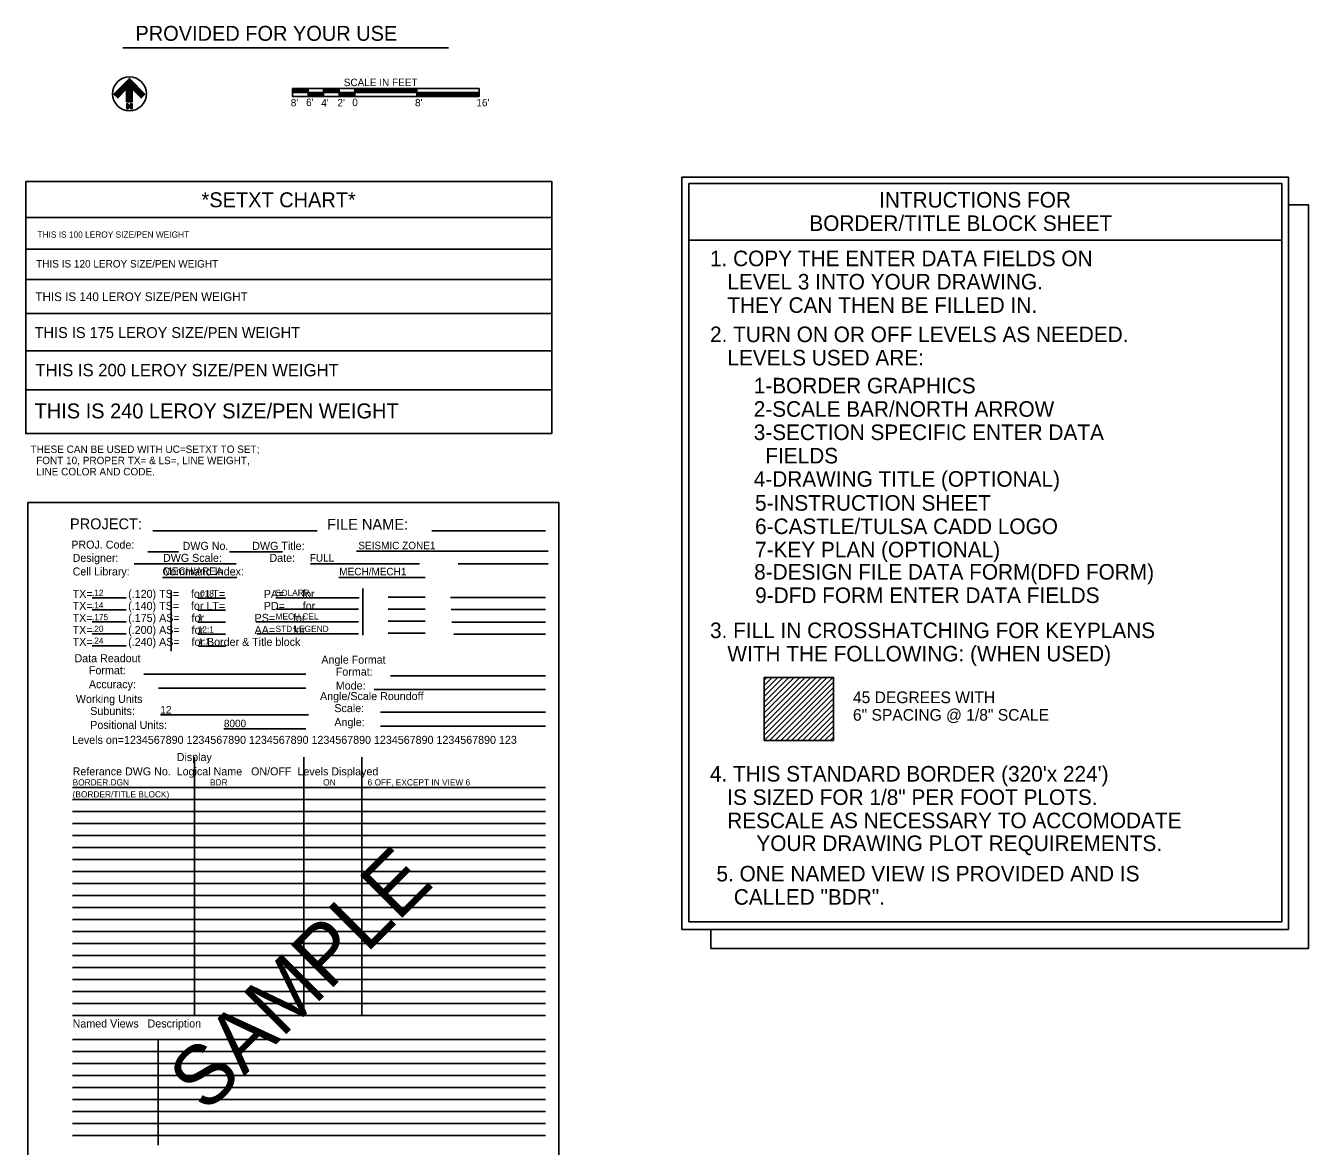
# Model space of a CAD drawing. Extents: x 10040.55 to 10045.84, y 10033.26 to 10035.76.
# Drawn here: x 10044.118 to 10045.836, y 10034.254 to 10035.755 of the extents above; entities that cross this region are included whole.
import ezdxf

# ---------------------------------------------------------------- set-up
doc = ezdxf.new("R2010")
doc.units = 0
for name, color, linetype in [('Level 1', 7, 'Continuous'), ('Level 2', 7, 'Continuous'), ('Level 5', 7, 'Continuous'), ('Level 8', 7, 'Continuous'), ('Level 9', 7, 'Continuous')]:
    doc.layers.add(name, color=color, linetype=linetype)

msp = doc.modelspace()

# ---------------------------------------------------------------- linework, layer by layer
at = {"layer": 'Level 2'}
for p, q in [((10044.2569, 10035.6528), (10044.2569, 10035.6841)), ((10044.4753, 10035.6705), (10044.7253, 10035.6705)), ((10044.4753, 10035.6705), (10044.4753, 10035.6601)), ((10044.4753, 10035.67), (10044.4961, 10035.67)), ((10044.4753, 10035.6691), (10044.4961, 10035.6691)), ((10044.4753, 10035.6683), (10044.4961, 10035.6683)), ((10044.4753, 10035.6674), (10044.4961, 10035.6674)), ((10044.4753, 10035.6665), (10044.4961, 10035.6665)), ((10044.4753, 10035.6657), (10044.4961, 10035.6657)), ((10044.4753, 10035.6653), (10044.7253, 10035.6653)), ((10044.4961, 10035.6705), (10044.4961, 10035.6601)), ((10044.4961, 10035.6649), (10044.5169, 10035.6649)), ((10044.4961, 10035.664), (10044.5169, 10035.664)), ((10044.5169, 10035.6705), (10044.5169, 10035.6601)), ((10044.5169, 10035.67), (10044.5377, 10035.67)), ((10044.5169, 10035.6691), (10044.5377, 10035.6691)), ((10044.5169, 10035.6682), (10044.5377, 10035.6682)), ((10044.5169, 10035.6674), (10044.5377, 10035.6674)), ((10044.5169, 10035.6665), (10044.5377, 10035.6665)), ((10044.5169, 10035.6656), (10044.5377, 10035.6656)), ((10044.5377, 10035.6648), (10044.5586, 10035.6648)), ((10044.5377, 10035.664), (10044.5586, 10035.664)), ((10044.5378, 10035.6705), (10044.5378, 10035.6601)), ((10044.5586, 10035.6705), (10044.5586, 10035.6601)), ((10044.5586, 10035.6699), (10044.6419, 10035.6699)), ((10044.5586, 10035.669), (10044.6419, 10035.669)), ((10044.5586, 10035.6681), (10044.6419, 10035.6681)), ((10044.5586, 10035.6673), (10044.6419, 10035.6673)), ((10044.5586, 10035.6664), (10044.6419, 10035.6664)), ((10044.6419, 10035.6705), (10044.6419, 10035.6601)), ((10044.6419, 10035.6645), (10044.7252, 10035.6645)), ((10044.7253, 10035.6705), (10044.7253, 10035.6601)), ((10044.254, 10035.6436), (10044.254, 10035.6501)), ((10044.2546, 10035.6436), (10044.2546, 10035.6501)), ((10044.2546, 10035.6498), (10044.2592, 10035.644)), ((10044.2592, 10035.6436), (10044.2592, 10035.6501)), ((10044.2598, 10035.6436), (10044.2598, 10035.6501)), ((10044.4753, 10035.6601), (10044.7253, 10035.6601)), ((10044.4961, 10035.6631), (10044.5169, 10035.6631)), ((10044.4961, 10035.6623), (10044.5169, 10035.6623)), ((10044.4961, 10035.6614), (10044.5169, 10035.6614)), ((10044.4961, 10035.6605), (10044.5169, 10035.6605)), ((10044.5377, 10035.6631), (10044.5586, 10035.6631)), ((10044.5377, 10035.6622), (10044.5586, 10035.6622)), ((10044.5377, 10035.6614), (10044.5586, 10035.6614)), ((10044.5377, 10035.6605), (10044.5586, 10035.6605)), ((10044.6419, 10035.6636), (10044.7252, 10035.6636)), ((10044.6419, 10035.6628), (10044.7252, 10035.6628)), ((10044.6419, 10035.6619), (10044.7252, 10035.6619)), ((10044.6419, 10035.661), (10044.7252, 10035.661))]:
    msp.add_line(p, q, dxfattribs=at)
for points in [[(10044.2606, 10035.6528), (10044.2606, 10035.67), (10044.2725, 10035.658), (10044.2777, 10035.6632), (10044.2569, 10035.6841), (10044.2361, 10035.6632), (10044.2413, 10035.658), (10044.2532, 10035.67), (10044.2532, 10035.6528)], [(10044.2534, 10035.6436), (10044.2534, 10035.6501), (10044.2548, 10035.6501), (10044.2586, 10035.6454), (10044.2586, 10035.6501), (10044.2604, 10035.6501), (10044.2604, 10035.6436), (10044.2589, 10035.6436), (10044.2552, 10035.6484), (10044.2552, 10035.6436)]]:
    msp.add_lwpolyline(points, close=True, dxfattribs=at)
for points in [[(10044.2367, 10035.6626), (10044.2569, 10035.6828), (10044.2771, 10035.6626)], [(10044.2374, 10035.6619), (10044.2569, 10035.6815), (10044.2764, 10035.6619)], [(10044.238, 10035.6613), (10044.2569, 10035.6802), (10044.2758, 10035.6613)], [(10044.2387, 10035.6606), (10044.2569, 10035.6789), (10044.2751, 10035.6606)], [(10044.256, 10035.6528), (10044.256, 10035.6767), (10044.2393, 10035.66)], [(10044.255, 10035.6528), (10044.255, 10035.6744), (10044.24, 10035.6593)], [(10044.2541, 10035.6528), (10044.2541, 10035.6722), (10044.2406, 10035.6587)], [(10044.2532, 10035.6528), (10044.2532, 10035.67), (10044.2413, 10035.658)], [(10044.2578, 10035.6528), (10044.2578, 10035.6767), (10044.2745, 10035.66)], [(10044.2587, 10035.6528), (10044.2587, 10035.6744), (10044.2738, 10035.6593)], [(10044.2597, 10035.6528), (10044.2597, 10035.6722), (10044.2732, 10035.6587)]]:
    msp.add_lwpolyline(points, dxfattribs=at)
msp.add_circle((10044.257, 10035.6635), 0.0227, dxfattribs=at)
at = {"layer": 'Level 5'}
for p, q in [((10044.2483, 10035.7253), (10044.6844, 10035.7253)), ((10044.118, 10035.4979), (10044.8225, 10035.4979)), ((10045.0062, 10035.4674), (10045.8002, 10035.4674)), ((10044.118, 10035.4554), (10044.8225, 10035.4554)), ((10044.118, 10035.4147), (10044.8225, 10035.4147)), ((10044.118, 10035.3693), (10044.8225, 10035.3693)), ((10044.118, 10035.3192), (10044.8225, 10035.3192)), ((10044.118, 10035.2672), (10044.8225, 10035.2672)), ((10045.1067, 10034.8342), (10045.1546, 10034.882)), ((10045.1067, 10034.8121), (10045.1766, 10034.8819)), ((10045.1068, 10034.8564), (10045.1325, 10034.8821)), ((10045.1068, 10034.8048), (10045.184, 10034.8819)), ((10045.1068, 10034.8637), (10045.1248, 10034.8817)), ((10045.1069, 10034.8418), (10045.1473, 10034.8821)), ((10045.1069, 10034.8786), (10045.1104, 10034.8821)), ((10045.1069, 10034.8491), (10045.1399, 10034.882)), ((10045.1069, 10034.8712), (10045.1177, 10034.882)), ((10045.1069, 10034.8196), (10045.169, 10034.8817)), ((10045.107, 10034.7976), (10045.1915, 10034.8821)), ((10045.107, 10034.8271), (10045.1619, 10034.882)), ((10045.1142, 10034.7974), (10045.1988, 10034.8821)), ((10045.1216, 10034.7974), (10045.1997, 10034.8756)), ((10045.1293, 10034.7978), (10045.1996, 10034.8681)), ((10045.1365, 10034.7977), (10045.1996, 10034.8608)), ((10045.1438, 10034.7976), (10045.1995, 10034.8533)), ((10045.1511, 10034.7976), (10045.1995, 10034.846)), ((10045.1584, 10034.7975), (10045.1995, 10034.8386)), ((10045.1658, 10034.7975), (10045.1998, 10034.8315)), ((10045.1731, 10034.7975), (10045.1996, 10034.824)), ((10045.1804, 10034.7973), (10045.1998, 10034.8167)), ((10045.188, 10034.7976), (10045.1997, 10034.8093)), ((10045.1953, 10034.7976), (10045.1998, 10034.802))]:
    msp.add_line(p, q, dxfattribs=at)
for points in [[(10044.118, 10035.5462), (10044.8225, 10035.5462), (10044.8225, 10035.2086), (10044.118, 10035.2086), (10044.118, 10035.5462)], [(10044.9969, 10035.552), (10045.8091, 10035.552), (10045.8091, 10034.5446), (10044.9969, 10034.5446), (10044.9969, 10035.552)], [(10045.0062, 10035.5436), (10045.8002, 10035.5436), (10045.8002, 10034.5547), (10045.0062, 10034.5547), (10045.0062, 10035.5436)], [(10045.8091, 10035.515), (10045.8358, 10035.515), (10045.8358, 10034.5191), (10045.0356, 10034.5191), (10045.0356, 10034.5446)]]:
    msp.add_lwpolyline(points, dxfattribs=at)
msp.add_lwpolyline([(10045.107, 10034.7976), (10045.107, 10034.8821), (10045.1998, 10034.8821), (10045.1998, 10034.7976)], close=True, dxfattribs=at)
at = {"layer": 'Level 8'}
for p, q in [((10044.1209, 10033.283), (10044.1209, 10035.1163)), ((10044.1209, 10035.1163), (10044.832, 10035.1163)), ((10044.832, 10035.1163), (10044.832, 10033.283)), ((10044.5083, 10035.0783), (10044.2883, 10035.0783)), ((10044.814, 10035.0783), (10044.6621, 10035.0783)), ((10044.3228, 10035.0504), (10044.2814, 10035.0504)), ((10044.4619, 10035.0504), (10044.3911, 10035.0504)), ((10044.8176, 10035.0511), (10044.5611, 10035.0511)), ((10044.2634, 10035.0342), (10044.3998, 10035.0342)), ((10044.4996, 10035.0342), (10044.6454, 10035.0342)), ((10044.6974, 10035.0342), (10044.8176, 10035.0342)), ((10044.3012, 10035.016), (10044.401, 10035.016)), ((10044.5374, 10035.016), (10044.6531, 10035.016)), ((10044.3127, 10034.9971), (10044.3127, 10034.9174)), ((10044.5696, 10034.9386), (10044.5696, 10035.0013)), ((10044.2524, 10034.9886), (10044.2071, 10034.9886)), ((10044.3855, 10034.9881), (10044.3485, 10034.9881)), ((10044.5644, 10034.9888), (10044.4531, 10034.9888)), ((10044.6532, 10034.9895), (10044.6033, 10034.9895)), ((10044.814, 10034.9889), (10044.6869, 10034.9889)), ((10044.2524, 10034.9725), (10044.2071, 10034.9725)), ((10044.3855, 10034.9721), (10044.3485, 10034.9721)), ((10044.5639, 10034.9733), (10044.4543, 10034.9733)), ((10044.6532, 10034.9734), (10044.6033, 10034.9734)), ((10044.814, 10034.9729), (10044.688, 10034.9729)), ((10044.2524, 10034.9564), (10044.2071, 10034.9564)), ((10044.3855, 10034.956), (10044.3485, 10034.956)), ((10044.5639, 10034.9567), (10044.4266, 10034.9567)), ((10044.6532, 10034.9573), (10044.6033, 10034.9573)), ((10044.814, 10034.9562), (10044.6885, 10034.9562)), ((10044.2524, 10034.9403), (10044.2071, 10034.9403)), ((10044.3855, 10034.9399), (10044.3485, 10034.9399)), ((10044.5639, 10034.9406), (10044.4277, 10034.9406)), ((10044.6532, 10034.9412), (10044.6033, 10034.9412)), ((10044.814, 10034.9402), (10044.6913, 10034.9402)), ((10044.2524, 10034.9243), (10044.2071, 10034.9243)), ((10044.3855, 10034.9238), (10044.3496, 10034.9238)), ((10044.493, 10034.8863), (10044.2763, 10034.8863)), ((10044.6066, 10034.8844), (10044.814, 10034.8844)), ((10044.493, 10034.8676), (10044.2958, 10034.8676)), ((10044.814, 10034.8658), (10044.5845, 10034.8658)), ((10044.4966, 10034.8318), (10044.2984, 10034.8318)), ((10044.814, 10034.8356), (10044.593, 10034.8356)), ((10044.493, 10034.8131), (10044.3836, 10034.8131)), ((10044.814, 10034.8169), (10044.593, 10034.8169)), ((10044.3441, 10034.7754), (10044.3441, 10034.4294)), ((10044.4904, 10034.7754), (10044.4904, 10034.4305)), ((10044.5681, 10034.7754), (10044.5681, 10034.4294)), ((10044.814, 10034.7348), (10044.1809, 10034.7348)), ((10044.814, 10034.7188), (10044.1809, 10034.7188)), ((10044.814, 10034.7027), (10044.1809, 10034.7027)), ((10044.814, 10034.6866), (10044.1809, 10034.6866)), ((10044.814, 10034.6705), (10044.1809, 10034.6705)), ((10044.814, 10034.6545), (10044.1809, 10034.6545)), ((10044.814, 10034.6384), (10044.1809, 10034.6384)), ((10044.814, 10034.6223), (10044.1809, 10034.6223)), ((10044.814, 10034.6062), (10044.1809, 10034.6062)), ((10044.814, 10034.5902), (10044.1809, 10034.5902)), ((10044.814, 10034.5741), (10044.1809, 10034.5741)), ((10044.814, 10034.558), (10044.1809, 10034.558)), ((10044.814, 10034.5419), (10044.1809, 10034.5419)), ((10044.814, 10034.5259), (10044.1809, 10034.5259)), ((10044.814, 10034.5098), (10044.1809, 10034.5098)), ((10044.814, 10034.4937), (10044.1809, 10034.4937)), ((10044.814, 10034.4776), (10044.1809, 10034.4776)), ((10044.814, 10034.4616), (10044.1809, 10034.4616)), ((10044.814, 10034.4455), (10044.1809, 10034.4455)), ((10044.814, 10034.4294), (10044.1809, 10034.4294)), ((10044.814, 10034.3973), (10044.1809, 10034.3973)), ((10044.2953, 10034.3973), (10044.2953, 10034.2558)), ((10044.814, 10034.3812), (10044.1809, 10034.3812)), ((10044.814, 10034.3651), (10044.1809, 10034.3651)), ((10044.814, 10034.349), (10044.1809, 10034.349)), ((10044.814, 10034.3329), (10044.1809, 10034.3329)), ((10044.814, 10034.3169), (10044.1809, 10034.3169)), ((10044.814, 10034.3008), (10044.1809, 10034.3008)), ((10044.814, 10034.2847), (10044.1809, 10034.2847)), ((10044.814, 10034.2686), (10044.1809, 10034.2686))]:
    msp.add_line(p, q, dxfattribs=at)

# ---------------------------------------------------------------- texts
at = {"layer": 'Level 1'}
msp.add_text('SAMPLE', height=0.08, rotation=45, dxfattribs=at).set_placement((10044.3598, 10034.2973))
at = {"layer": 'Level 2'}
for s, p in [('SCALE IN FEET', (10044.544, 10035.6738)), ("8'", (10044.473, 10035.6467)), ("6'", (10044.4935, 10035.647)), ("4'", (10044.5138, 10035.6464)), ("2'", (10044.5355, 10035.6467)), ('0', (10044.5554, 10035.647)), ("8'", (10044.6394, 10035.6467)), ("16'", (10044.7216, 10035.6467))]:
    msp.add_text(s, height=0.01, dxfattribs=at).set_placement(p)
at = {"layer": 'Level 5'}
for s, height, p in [('PROVIDED FOR YOUR USE', 0.02, (10044.265, 10035.7345)), ('*SETXT CHART*', 0.02, (10044.3535, 10035.5116)), ('INTRUCTIONS FOR', 0.020833, (10045.2609, 10035.5112)), ('BORDER/TITLE BLOCK SHEET', 0.020833, (10045.1675, 10035.4799)), ('THIS IS 100 LEROY SIZE/PEN WEIGHT', 0.008333, (10044.1338, 10035.4709)), ('THIS IS 120 LEROY SIZE/PEN WEIGHT', 0.01, (10044.1321, 10035.4309)), ('1. COPY THE ENTER DATA FIELDS ON', 0.020833, (10045.0344, 10035.4327)), ('   LEVEL 3 INTO YOUR DRAWING.', 0.020833, (10045.0344, 10035.4015)), ('THIS IS 140 LEROY SIZE/PEN WEIGHT', 0.011667, (10044.131, 10035.386)), ('   THEY CAN THEN BE FILLED IN.', 0.020833, (10045.0344, 10035.3702)), ('THIS IS 175 LEROY SIZE/PEN WEIGHT', 0.014583, (10044.13, 10035.3365)), ('2. TURN ON OR OFF LEVELS AS NEEDED.', 0.020833, (10045.0345, 10035.331)), ('   LEVELS USED ARE:', 0.020833, (10045.0345, 10035.2998)), ('THIS IS 200 LEROY SIZE/PEN WEIGHT', 0.016667, (10044.131, 10035.2852)), ('1-BORDER GRAPHICS', 0.020833, (10045.093, 10035.2624)), ('2-SCALE BAR/NORTH ARROW', 0.020833, (10045.093, 10035.2311)), ('THIS IS 240 LEROY SIZE/PEN WEIGHT', 0.02, (10044.13, 10035.2289)), ('3-SECTION SPECIFIC ENTER DATA', 0.020833, (10045.093, 10035.1999)), ('THESE CAN BE USED WITH UC=SETXT TO SET;', 0.01, (10044.1246, 10035.1826)), ('  FIELDS', 0.02083, (10045.093, 10035.1686)), ('  FONT 10, PROPER TX= & LS=, LINE WEIGHT,', 0.01, (10044.1246, 10035.1676)), ('  LINE COLOR AND CODE.', 0.01, (10044.1246, 10035.1526)), ('4-DRAWING TITLE (OPTIONAL)', 0.020833, (10045.093, 10035.1374)), ('5-INSTRUCTION SHEET', 0.020833, (10045.0948, 10035.1053)), ('6-CASTLE/TULSA CADD LOGO', 0.020833, (10045.0948, 10035.074)), ('7-KEY PLAN (OPTIONAL)', 0.020833, (10045.0948, 10035.0428)), ('8-DESIGN FILE DATA FORM(DFD FORM)', 0.020833, (10045.0936, 10035.013)), ('9-DFD FORM ENTER DATA FIELDS', 0.020833, (10045.0949, 10034.9817)), ('3. FILL IN CROSSHATCHING FOR KEYPLANS', 0.020833, (10045.0345, 10034.9347)), ('   WITH THE FOLLOWING: (WHEN USED)', 0.020833, (10045.0345, 10034.9035)), ('45 DEGREES WITH', 0.015625, (10045.2259, 10034.8476)), ('6" SPACING @ 1/8" SCALE', 0.015625, (10045.2259, 10034.8241)), ("4. THIS STANDARD BORDER (320'x 224')", 0.020833, (10045.0343, 10034.7426)), ('   IS SIZED FOR 1/8" PER FOOT PLOTS.', 0.020833, (10045.0343, 10034.7113)), ('   RESCALE AS NECESSARY TO ACCOMODATE', 0.020833, (10045.0343, 10034.6801)), ('YOUR DRAWING PLOT REQUIREMENTS.', 0.020833, (10045.0966, 10034.6496)), ('5. ONE NAMED VIEW IS PROVIDED AND IS', 0.020833, (10045.0431, 10034.6089)), ('   CALLED "BDR".', 0.020833, (10045.0431, 10034.5777))]:
    msp.add_text(s, height=height, dxfattribs=at).set_placement(p)
at = {"layer": 'Level 8'}
for s, height, p in [('PROJECT:', 0.01459, (10044.1773, 10035.0804)), ('FILE NAME:', 0.01459, (10044.5217, 10035.0798)), ('PROJ. Code:', 0.010717, (10044.1791, 10035.0545)), ('DWG No.        DWG Title:', 0.010717, (10044.3282, 10035.0529)), ('Designer:               DWG Scale:                Date:', 0.010717, (10044.1809, 10035.0368)), ('Cell Library:           Command Index:', 0.010717, (10044.1809, 10035.0186)), ('TX=', 0.01072, (10044.1809, 10034.9886)), ('(.120) TS=    for LT=             PA=      for', 0.010717, (10044.2553, 10034.9886)), ('TX=', 0.01072, (10044.1809, 10034.9725)), ('(.140) TS=    for LT=             PD=      for', 0.010717, (10044.2553, 10034.9725)), ('TX=', 0.01072, (10044.1809, 10034.9564)), ('(.175) AS=    for                 PS=      for', 0.010717, (10044.2553, 10034.9564)), ('TX=', 0.01072, (10044.1809, 10034.9403)), ('(.200) AS=    for                 AA=      for', 0.010717, (10044.2553, 10034.9403)), ('TX=', 0.01072, (10044.1809, 10034.9243)), ('(.240) AS=    for Border & Title block', 0.010717, (10044.2553, 10034.9243)), ('Data Readout', 0.010717, (10044.1834, 10034.9024)), ('Angle Format', 0.010717, (10044.514, 10034.9005)), ('Format:', 0.01072, (10044.2027, 10034.8863)), ('Format:', 0.01072, (10044.5333, 10034.8844)), ('Accuracy:', 0.01072, (10044.2027, 10034.8676)), ('Mode:', 0.01072, (10044.5333, 10034.8658)), ('Working Units', 0.010717, (10044.1852, 10034.8479)), ('Angle/Scale Roundoff', 0.010717, (10044.5122, 10034.8517)), ('Subunits:', 0.01072, (10044.2045, 10034.8318)), ('Scale:', 0.01072, (10044.5314, 10034.8356)), ('Positional Units:', 0.010717, (10044.2045, 10034.8131)), ('Angle:', 0.01072, (10044.5314, 10034.8169)), ('Levels on=1234567890 1234567890 1234567890 1234567890 1234567890 1234567890 123', 0.010717, (10044.18, 10034.7931)), ('                                 Display ', 0.010717, (10044.1889, 10034.7701)), ('Referance DWG No.  Logical Name   ON/OFF  Levels Displayed', 0.010717, (10044.1809, 10034.7509)), ('Named Views   Description', 0.010717, (10044.1809, 10034.4133))]:
    msp.add_text(s, height=height, dxfattribs=at).set_placement(p)
at = {"layer": 'Level 9'}
for s, height, p in [('SEISMIC ZONE1             ', 0.010001, (10044.5635, 10035.0537)), ('FULL          ', 0.010001, (10044.4985, 10035.0371)), ('MECH/AREA', 0.01, (10044.3024, 10035.0194)), ('MECH/MECH1 ', 0.01, (10044.538, 10035.0188)), ('.12 ', 0.00833, (10044.2068, 10034.9912)), ('.018', 0.00833, (10044.3484, 10034.9904)), ('SOLARR      ', 0.008331, (10044.4526, 10034.9912)), ('.14 ', 0.00833, (10044.2068, 10034.9746)), ('.175', 0.00833, (10044.2068, 10034.9587)), ('1   ', 0.00833, (10044.3484, 10034.9587)), ('MECH.CEL    ', 0.008331, (10044.4526, 10034.9596)), ('.20 ', 0.00833, (10044.2068, 10034.9429)), ('12:1', 0.00833, (10044.3484, 10034.9421)), ('STD LEGEND  ', 0.008331, (10044.4526, 10034.9429)), ('.24 ', 0.00833, (10044.2068, 10034.9271)), ('1:1 ', 0.00833, (10044.3493, 10034.9262)), ('12                  ', 0.010001, (10044.2984, 10034.8337)), ('8000     ', 0.01, (10044.3835, 10034.8154)), ('BORDER.DGN          ', 0.008333, (10044.1809, 10034.7374)), ('BDR       ', 0.00833, (10044.3649, 10034.7374)), ('ON ', 0.00833, (10044.5164, 10034.7374)), ('6 OFF, EXCEPT IN VIEW 6       ', 0.008333, (10044.5759, 10034.7374)), ('(BORDER/TITLE BLOCK)', 0.008333, (10044.1809, 10034.7214))]:
    msp.add_text(s, height=height, dxfattribs=at).set_placement(p)

doc.saveas('drawing.dxf')
